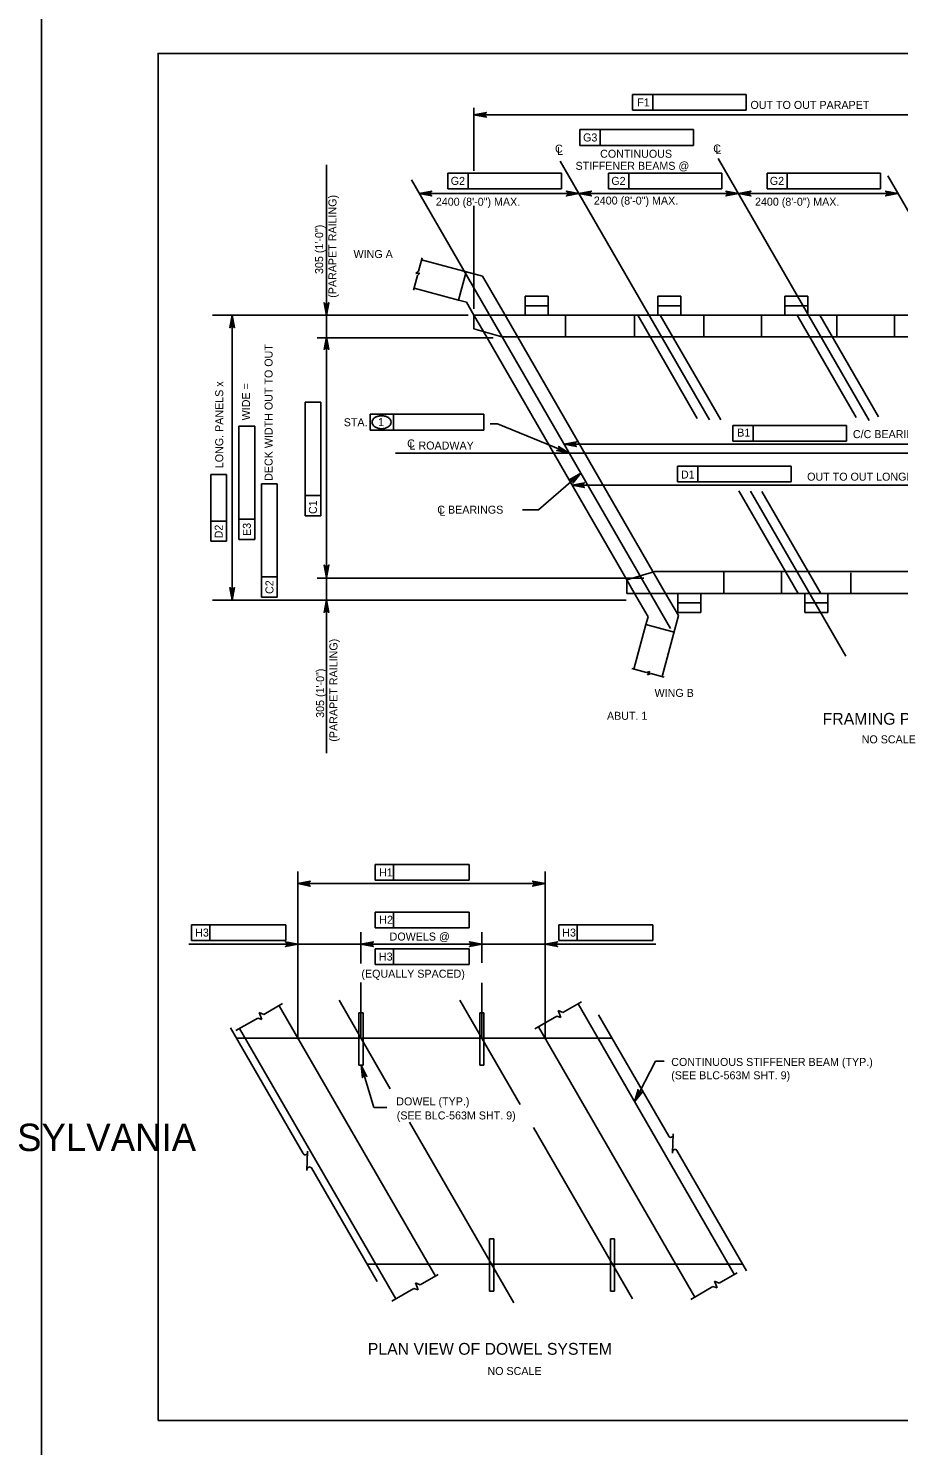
# Model space of a CAD drawing. Extents: x -8 to 75, y -110 to 0.
# Drawn here: x 33.8 to 46.85, y -65.62 to -44.38 of the extents above; entities that cross this region are included whole.
import ezdxf

# ---------------------------------------------------------------- set-up
doc = ezdxf.new("R2010")
doc.units = 0
for name, color, linetype in [('1', 7, 'Continuous'), ('2', 7, 'Continuous'), ('3', 7, 'Continuous'), ('4', 7, 'Continuous'), ('63', 7, 'Continuous')]:
    doc.layers.add(name, color=color, linetype=linetype)

# ---------------------------------------------------------------- blocks, each defined once
blk = doc.blocks.new('D')
at = {"layer": '3'}
for p, q in [((-0.324, 0.383), (-0.383, 0.324)), ((0.349, -0.408), (-0.383, 0.324)), ((0.408, -0.349), (-0.324, 0.383)), ((0.408, -0.349), (0.349, -0.408))]:
    blk.add_line(p, q, dxfattribs=at)

msp = doc.modelspace()

# ---------------------------------------------------------------- linework, layer by layer
at = {"layer": '1'}
msp.add_lwpolyline([(35.75, -65.25), (67.25, -65.25), (67.25, -44.75), (35.75, -44.75)], close=True, dxfattribs=at)
at = {"layer": '2'}
for p, q in [((40.615, -48.093), (39.7, -47.848)), ((40.255, -48.448), (40.367, -48.026)), ((40.953, -48.677), (40.615, -48.093)), ((40.255, -48.448), (39.587, -48.269)), ((40.373, -48.48), (40.255, -48.448)), ((41.252, -48.388), (41.252, -48.677)), ((41.598, -48.388), (41.252, -48.388)), ((41.598, -48.388), (41.598, -48.677)), ((43.588, -48.388), (43.242, -48.388)), ((43.242, -48.388), (43.242, -48.677)), ((43.588, -48.388), (43.588, -48.677)), ((45.146, -48.388), (45.492, -48.388)), ((45.146, -48.388), (45.146, -48.677)), ((45.492, -48.388), (45.492, -48.677)), ((40.373, -48.48), (40.486, -48.677)), ((40.486, -48.677), (48.247, -48.677)), ((40.486, -48.677), (40.627, -48.92)), ((40.486, -48.879), (40.486, -48.677)), ((40.953, -48.677), (43.359, -52.846)), ((40.906, -49.001), (40.486, -48.879)), ((40.627, -48.92), (42.777, -52.644)), ((47.828, -49.001), (40.906, -49.001)), ((43.196, -52.521), (42.777, -52.644)), ((42.777, -52.644), (42.777, -52.846)), ((42.777, -52.644), (42.893, -52.846)), ((50.118, -52.521), (43.196, -52.521)), ((42.777, -52.846), (50.537, -52.846)), ((42.893, -52.846), (43.096, -53.196)), ((43.552, -53.179), (43.359, -52.846)), ((43.542, -53.134), (43.542, -52.846)), ((43.888, -53.134), (43.888, -52.846)), ((45.445, -53.134), (45.445, -52.846)), ((45.791, -53.134), (45.791, -52.846)), ((43.064, -53.315), (42.885, -53.982)), ((43.096, -53.196), (43.064, -53.315)), ((43.064, -53.315), (43.486, -53.427)), ((43.552, -53.179), (43.307, -54.095)), ((43.888, -53.134), (43.542, -53.134)), ((45.791, -53.134), (45.445, -53.134)), ((42.557, -59.516), (36.923, -59.516)), ((44.515, -62.904), (38.882, -62.904))]:
    msp.add_line(p, q, dxfattribs=at)
at = {"layer": '3'}
for p, q in [((39.655, -48.018), (39.614, -48.049)), ((39.655, -48.018), (39.708, -47.818)), ((39.579, -48.302), (39.637, -48.083)), ((39.614, -48.049), (39.672, -48.045)), ((39.672, -48.045), (39.637, -48.083)), ((41.598, -48.533), (41.252, -48.533)), ((43.588, -48.533), (43.242, -48.533)), ((45.146, -48.533), (45.492, -48.533)), ((41.857, -49.001), (41.857, -48.677)), ((42.895, -49.001), (42.895, -48.677)), ((42.941, -48.677), (43.834, -50.224)), ((43.279, -48.677), (44.186, -50.247)), ((43.934, -49.001), (43.934, -48.677)), ((44.799, -49.001), (44.799, -48.677)), ((45.333, -48.677), (46.218, -50.209)), ((45.672, -48.677), (46.551, -50.199)), ((45.925, -49.001), (45.925, -48.677)), ((46.79, -49.001), (46.79, -48.677)), ((44.46, -51.309), (45.348, -52.846)), ((44.804, -51.319), (45.686, -52.846)), ((44.234, -52.521), (44.234, -52.846)), ((45.099, -52.521), (45.099, -52.846)), ((46.138, -52.846), (46.138, -52.537)), ((43.888, -52.99), (43.542, -52.99)), ((45.791, -52.99), (45.445, -52.99)), ((42.853, -53.973), (43.072, -54.032)), ((43.122, -54.02), (43.072, -54.032)), ((43.09, -54.069), (43.122, -54.02)), ((43.137, -54.049), (43.09, -54.069)), ((43.137, -54.049), (43.337, -54.103)), ((37.337, -59.159), (37.617, -58.997)), ((37.563, -59.029), (39.907, -63.083)), ((39.23, -60.274), (38.464, -58.947)), ((41.181, -60.512), (40.276, -58.947)), ((41.82, -59.133), (42.1, -58.97)), ((42.046, -59.002), (44.39, -63.056)), ((36.917, -59.402), (37.243, -59.214)), ((37.243, -59.214), (37.305, -59.234)), ((37.305, -59.234), (37.265, -59.13)), ((37.265, -59.13), (37.337, -59.159)), ((41.4, -59.375), (41.726, -59.187)), ((41.726, -59.187), (41.788, -59.207)), ((41.748, -59.103), (41.82, -59.133)), ((41.788, -59.207), (41.748, -59.103)), ((42.354, -59.165), (43.406, -60.984)), ((36.833, -59.36), (37.924, -61.247)), ((39.313, -63.426), (36.97, -59.371)), ((43.797, -63.399), (41.453, -59.344)), ((38.76, -59.516), (38.823, -59.516)), ((40.573, -59.516), (40.636, -59.516)), ((41.086, -63.485), (39.52, -60.774)), ((42.863, -63.422), (41.378, -60.854)), ((43.474, -60.948), (43.463, -61.239)), ((43.53, -61.2), (44.573, -63.003)), ((37.992, -61.21), (37.982, -61.501)), ((38.048, -61.462), (39.032, -63.164)), ((39.68, -63.214), (39.948, -63.059)), ((44.163, -63.187), (44.431, -63.032)), ((39.254, -63.46), (39.586, -63.268)), ((39.586, -63.268), (39.649, -63.288)), ((39.608, -63.184), (39.68, -63.214)), ((39.649, -63.288), (39.608, -63.184)), ((43.737, -63.433), (44.07, -63.241)), ((44.07, -63.241), (44.132, -63.261)), ((44.091, -63.157), (44.163, -63.187)), ((44.132, -63.261), (44.091, -63.157))]:
    msp.add_line(p, q, dxfattribs=at)
for centre, start, end in [((43.437, -60.966), 210.0292, 0.0292), ((43.501, -61.221), 35.3578, 177.8964), ((37.956, -61.229), 210.0292, 0.0292), ((38.019, -61.483), 35.3578, 177.8964)]:
    msp.add_arc(centre, 0.0364, start, end, dxfattribs=at)
at = {"layer": '4'}
for p, q in [((42.865, -45.367), (44.566, -45.367)), ((42.865, -45.367), (42.865, -45.604)), ((43.167, -45.367), (43.167, -45.604)), ((44.566, -45.367), (44.566, -45.604)), ((40.486, -46.51), (40.486, -45.569)), ((40.486, -45.671), (48.247, -45.671)), ((42.865, -45.604), (44.566, -45.604)), ((42.075, -45.893), (43.776, -45.893)), ((42.075, -45.893), (42.075, -46.13)), ((42.378, -45.893), (42.378, -46.13)), ((43.776, -45.893), (43.776, -46.13)), ((42.075, -46.13), (43.776, -46.13)), ((44.147, -46.324), (46.412, -50.253)), ((38.274, -46.42), (38.274, -55.241)), ((41.779, -46.367), (44.016, -50.246)), ((43.432, -53.374), (39.548, -46.647)), ((40.095, -46.544), (41.796, -46.544)), ((40.095, -46.544), (40.095, -46.78)), ((40.398, -46.544), (40.398, -46.78)), ((41.796, -46.544), (41.796, -46.78)), ((42.503, -46.544), (44.204, -46.544)), ((42.503, -46.544), (42.503, -46.78)), ((42.806, -46.544), (42.806, -46.78)), ((44.204, -46.544), (44.204, -46.78)), ((44.881, -46.544), (46.582, -46.544)), ((44.881, -46.544), (44.881, -46.78)), ((45.183, -46.544), (45.183, -46.78)), ((46.582, -46.544), (46.582, -46.78)), ((50.637, -53.422), (46.69, -46.585)), ((39.666, -46.852), (46.844, -46.852)), ((40.095, -46.78), (41.796, -46.78)), ((42.503, -46.78), (44.204, -46.78)), ((44.881, -46.78), (46.582, -46.78)), ((40.486, -48.581), (40.486, -47.035)), ((40.401, -48.677), (36.564, -48.677)), ((36.86, -52.946), (36.86, -48.677)), ((40.772, -49.015), (38.134, -49.015)), ((37.953, -51.683), (37.953, -49.982)), ((38.19, -49.982), (37.953, -49.982)), ((38.19, -51.683), (38.19, -49.982)), ((36.962, -52.039), (36.962, -50.338)), ((37.198, -50.338), (36.962, -50.338)), ((37.198, -52.039), (37.198, -50.338)), ((38.931, -50.162), (40.632, -50.162)), ((38.931, -50.398), (38.931, -50.162)), ((39.281, -50.398), (39.281, -50.162)), ((40.632, -50.162), (40.632, -50.398)), ((40.84, -50.303), (40.73, -50.303)), ((40.843, -50.303), (40.73, -50.303)), ((41.914, -50.745), (40.84, -50.303)), ((44.369, -50.328), (46.07, -50.328)), ((44.369, -50.328), (44.369, -50.564)), ((44.672, -50.328), (44.672, -50.564)), ((46.07, -50.328), (46.07, -50.564)), ((40.632, -50.398), (38.931, -50.398)), ((44.369, -50.564), (46.07, -50.564)), ((51.399, -50.745), (39.31, -50.745)), ((41.836, -50.61), (49.014, -50.61)), ((43.539, -50.938), (45.24, -50.938)), ((43.539, -50.938), (43.539, -51.174)), ((43.842, -50.938), (43.842, -51.174)), ((45.24, -50.938), (45.24, -51.174)), ((36.54, -52.065), (36.54, -51.063)), ((36.776, -51.063), (36.54, -51.063)), ((36.776, -52.065), (36.776, -51.063)), ((37.301, -52.903), (37.301, -51.203)), ((37.537, -51.203), (37.301, -51.203)), ((37.537, -52.904), (37.537, -51.203)), ((41.453, -51.595), (42.086, -51.044)), ((43.539, -51.174), (45.24, -51.174)), ((38.19, -51.38), (37.953, -51.38)), ((41.956, -51.222), (49.6, -51.222)), ((44.633, -51.315), (46.06, -53.787)), ((41.214, -51.595), (41.453, -51.595)), ((36.776, -51.763), (36.54, -51.762)), ((37.198, -51.736), (36.962, -51.736)), ((37.953, -51.683), (38.19, -51.683)), ((36.962, -52.039), (37.198, -52.039)), ((36.54, -52.065), (36.776, -52.065)), ((37.537, -52.601), (37.301, -52.601)), ((43.035, -52.62), (38.134, -52.62)), ((37.301, -52.903), (37.537, -52.904)), ((42.77, -52.946), (36.564, -52.946)), ((39.003, -56.91), (40.415, -56.91)), ((39.003, -56.91), (39.003, -57.146)), ((39.278, -56.91), (39.278, -57.146)), ((40.415, -56.91), (40.415, -57.146)), ((37.844, -59.453), (37.844, -57.019)), ((40.415, -57.146), (39.003, -57.146)), ((41.552, -59.453), (41.552, -57.019)), ((41.552, -57.199), (37.844, -57.199)), ((39.003, -57.625), (39.003, -57.861)), ((39.003, -57.625), (40.415, -57.625)), ((39.278, -57.625), (39.278, -57.861)), ((40.415, -57.625), (40.415, -57.861)), ((36.252, -57.816), (37.664, -57.816)), ((36.252, -57.816), (36.252, -58.053)), ((36.527, -57.816), (36.527, -58.053)), ((37.664, -57.816), (37.664, -58.053)), ((37.844, -59.516), (37.844, -57.927)), ((38.791, -58.397), (38.791, -57.927)), ((40.415, -57.861), (39.003, -57.861)), ((40.604, -58.386), (40.604, -57.927)), ((41.552, -59.516), (41.552, -57.927)), ((41.757, -57.816), (43.169, -57.816)), ((41.757, -57.816), (41.757, -58.053)), ((42.033, -57.816), (42.033, -58.053)), ((43.169, -57.816), (43.169, -58.053)), ((37.724, -58.107), (36.209, -58.107)), ((37.664, -58.053), (36.252, -58.053)), ((38.791, -58.107), (37.843, -58.107)), ((40.484, -58.107), (38.911, -58.107)), ((39.003, -58.176), (40.415, -58.176)), ((39.003, -58.176), (39.003, -58.412)), ((39.278, -58.176), (39.278, -58.412)), ((40.484, -58.107), (40.364, -58.107)), ((40.415, -58.176), (40.415, -58.412)), ((41.552, -58.107), (40.604, -58.107)), ((41.672, -58.107), (43.215, -58.107)), ((43.169, -58.053), (41.757, -58.053)), ((40.415, -58.412), (39.003, -58.412)), ((38.791, -59.516), (38.791, -58.68)), ((40.604, -59.516), (40.604, -58.686)), ((43.209, -59.861), (43.339, -59.861)), ((38.987, -60.556), (39.181, -60.556))]:
    msp.add_line(p, q, dxfattribs=at)
for points in [[(40.486, -45.671), (40.673, -45.636), (40.658, -45.646), (40.651, -45.658), (40.649, -45.671), (40.651, -45.683), (40.658, -45.696), (40.673, -45.706), (40.486, -45.671), (40.658, -45.696), (40.651, -45.683), (40.486, -45.671), (40.649, -45.671), (40.651, -45.658), (40.486, -45.671), (40.658, -45.646)], [(39.666, -46.852), (39.853, -46.817), (39.838, -46.827), (39.831, -46.84), (39.829, -46.852), (39.831, -46.865), (39.838, -46.877), (39.853, -46.887), (39.666, -46.852), (39.838, -46.877), (39.831, -46.865), (39.666, -46.852), (39.829, -46.852), (39.831, -46.84), (39.666, -46.852), (39.838, -46.827)], [(42.059, -46.852), (41.873, -46.887), (41.887, -46.877), (41.895, -46.865), (41.897, -46.852), (41.895, -46.84), (41.887, -46.827), (41.873, -46.817), (42.059, -46.852), (41.887, -46.827), (41.895, -46.84), (42.059, -46.852), (41.897, -46.852), (41.895, -46.865), (42.059, -46.852), (41.887, -46.877)], [(42.059, -46.852), (42.246, -46.887), (42.231, -46.877), (42.224, -46.865), (42.222, -46.852), (42.224, -46.84), (42.231, -46.827), (42.246, -46.817), (42.059, -46.852), (42.231, -46.827), (42.224, -46.84), (42.059, -46.852), (42.222, -46.852), (42.224, -46.865), (42.059, -46.852), (42.231, -46.877)], [(44.452, -46.852), (44.265, -46.887), (44.28, -46.877), (44.287, -46.865), (44.289, -46.852), (44.287, -46.84), (44.28, -46.827), (44.265, -46.817), (44.452, -46.852), (44.28, -46.827), (44.287, -46.84), (44.452, -46.852), (44.289, -46.852), (44.287, -46.865), (44.452, -46.852), (44.28, -46.877)], [(44.452, -46.852), (44.638, -46.887), (44.624, -46.877), (44.616, -46.865), (44.614, -46.852), (44.616, -46.84), (44.624, -46.827), (44.638, -46.817), (44.452, -46.852), (44.624, -46.827), (44.616, -46.84), (44.452, -46.852), (44.614, -46.852), (44.616, -46.865), (44.452, -46.852), (44.624, -46.877)], [(46.844, -46.852), (46.657, -46.887), (46.672, -46.877), (46.679, -46.865), (46.681, -46.852), (46.679, -46.84), (46.672, -46.827), (46.657, -46.817), (46.844, -46.852), (46.672, -46.827), (46.679, -46.84), (46.844, -46.852), (46.681, -46.852), (46.679, -46.865), (46.844, -46.852), (46.672, -46.877)], [(38.274, -48.677), (38.239, -48.49), (38.249, -48.505), (38.261, -48.512), (38.274, -48.514), (38.286, -48.512), (38.299, -48.505), (38.309, -48.49), (38.274, -48.677), (38.299, -48.505), (38.286, -48.512), (38.274, -48.677), (38.274, -48.514), (38.261, -48.512), (38.274, -48.677), (38.249, -48.505)], [(36.86, -48.677), (36.895, -48.863), (36.885, -48.849), (36.873, -48.841), (36.86, -48.839), (36.848, -48.841), (36.835, -48.849), (36.825, -48.863), (36.86, -48.677), (36.835, -48.849), (36.848, -48.841), (36.86, -48.677), (36.86, -48.839), (36.873, -48.841), (36.86, -48.677), (36.885, -48.849)], [(38.274, -49.003), (38.309, -49.189), (38.299, -49.175), (38.286, -49.168), (38.274, -49.166), (38.261, -49.168), (38.249, -49.175), (38.239, -49.189), (38.274, -49.003), (38.249, -49.175), (38.261, -49.168), (38.274, -49.003), (38.274, -49.166), (38.286, -49.168), (38.274, -49.003), (38.299, -49.175)], [(41.914, -50.745), (41.728, -50.706), (41.745, -50.703), (41.757, -50.694), (41.763, -50.683), (41.766, -50.671), (41.764, -50.656), (41.755, -50.642), (41.914, -50.745), (41.764, -50.656), (41.766, -50.671), (41.914, -50.745), (41.763, -50.683), (41.757, -50.694), (41.914, -50.745), (41.745, -50.703)], [(41.836, -50.61), (42.022, -50.575), (42.008, -50.585), (42, -50.598), (41.998, -50.61), (42, -50.623), (42.008, -50.635), (42.022, -50.645), (41.836, -50.61), (42.008, -50.635), (42, -50.623), (41.836, -50.61), (41.998, -50.61), (42, -50.598), (41.836, -50.61), (42.008, -50.585)], [(42.086, -51.044), (41.969, -51.193), (41.973, -51.176), (41.97, -51.162), (41.964, -51.151), (41.954, -51.143), (41.94, -51.138), (41.923, -51.14), (42.086, -51.044), (41.94, -51.138), (41.954, -51.143), (42.086, -51.044), (41.964, -51.151), (41.97, -51.162), (42.086, -51.044), (41.973, -51.176)], [(41.956, -51.222), (42.142, -51.187), (42.128, -51.197), (42.121, -51.21), (42.118, -51.222), (42.121, -51.235), (42.128, -51.247), (42.142, -51.257), (41.956, -51.222), (42.128, -51.247), (42.121, -51.235), (41.956, -51.222), (42.118, -51.222), (42.121, -51.21), (41.956, -51.222), (42.128, -51.197)], [(38.276, -52.61), (38.241, -52.423), (38.251, -52.438), (38.263, -52.445), (38.276, -52.447), (38.288, -52.445), (38.301, -52.438), (38.31, -52.423), (38.276, -52.61), (38.301, -52.438), (38.288, -52.445), (38.276, -52.61), (38.276, -52.447), (38.263, -52.445), (38.276, -52.61), (38.251, -52.438)], [(36.86, -52.946), (36.825, -52.759), (36.835, -52.774), (36.848, -52.781), (36.86, -52.783), (36.873, -52.781), (36.885, -52.774), (36.895, -52.759), (36.86, -52.946), (36.885, -52.774), (36.873, -52.781), (36.86, -52.946), (36.86, -52.783), (36.848, -52.781), (36.86, -52.946), (36.835, -52.774)], [(38.274, -52.946), (38.309, -53.132), (38.299, -53.118), (38.286, -53.11), (38.274, -53.108), (38.261, -53.11), (38.249, -53.118), (38.239, -53.132), (38.274, -52.946), (38.249, -53.118), (38.261, -53.11), (38.274, -52.946), (38.274, -53.108), (38.286, -53.11), (38.274, -52.946), (38.299, -53.118)], [(37.844, -57.199), (38.031, -57.164), (38.017, -57.174), (38.009, -57.186), (38.007, -57.199), (38.009, -57.211), (38.017, -57.224), (38.031, -57.234), (37.844, -57.199), (38.017, -57.224), (38.009, -57.211), (37.844, -57.199), (38.007, -57.199), (38.009, -57.186), (37.844, -57.199), (38.017, -57.174)], [(41.552, -57.199), (41.366, -57.234), (41.38, -57.224), (41.387, -57.211), (41.39, -57.199), (41.387, -57.186), (41.38, -57.174), (41.366, -57.164), (41.552, -57.199), (41.38, -57.174), (41.387, -57.186), (41.552, -57.199), (41.39, -57.199), (41.387, -57.211), (41.552, -57.199), (41.38, -57.224)], [(37.844, -58.107), (37.658, -58.142), (37.672, -58.132), (37.68, -58.12), (37.682, -58.107), (37.68, -58.095), (37.672, -58.082), (37.658, -58.072), (37.844, -58.107), (37.672, -58.082), (37.68, -58.095), (37.844, -58.107), (37.682, -58.107), (37.68, -58.12), (37.844, -58.107), (37.672, -58.132)], [(38.791, -58.107), (38.978, -58.072), (38.963, -58.082), (38.956, -58.095), (38.954, -58.107), (38.956, -58.12), (38.963, -58.132), (38.978, -58.142), (38.791, -58.107), (38.963, -58.132), (38.956, -58.12), (38.791, -58.107), (38.954, -58.107), (38.956, -58.095), (38.791, -58.107), (38.963, -58.082)], [(40.604, -58.107), (40.418, -58.142), (40.432, -58.132), (40.439, -58.12), (40.442, -58.107), (40.439, -58.095), (40.432, -58.082), (40.418, -58.072), (40.604, -58.107), (40.432, -58.082), (40.439, -58.095), (40.604, -58.107), (40.442, -58.107), (40.439, -58.12), (40.604, -58.107), (40.432, -58.132)], [(41.552, -58.107), (41.739, -58.072), (41.724, -58.082), (41.717, -58.095), (41.715, -58.107), (41.717, -58.12), (41.724, -58.132), (41.739, -58.142), (41.552, -58.107), (41.724, -58.132), (41.717, -58.12), (41.552, -58.107), (41.715, -58.107), (41.717, -58.095), (41.552, -58.107), (41.724, -58.082)], [(38.792, -59.92), (38.986, -60.556)], [(38.792, -59.92), (38.813, -60.108), (38.819, -60.092), (38.828, -60.081), (38.84, -60.075), (38.852, -60.074), (38.867, -60.077), (38.88, -60.088), (38.792, -59.92), (38.867, -60.077), (38.852, -60.074), (38.792, -59.92), (38.84, -60.075), (38.828, -60.081), (38.792, -59.92), (38.819, -60.092)], [(42.894, -60.468), (43.209, -59.861)], [(42.894, -60.468), (43.011, -60.318), (42.995, -60.326), (42.98, -60.327), (42.968, -60.323), (42.958, -60.316), (42.951, -60.303), (42.948, -60.286), (42.894, -60.468), (42.951, -60.303), (42.958, -60.316), (42.894, -60.468), (42.968, -60.323), (42.98, -60.327), (42.894, -60.468), (42.995, -60.326)]]:
    msp.add_lwpolyline(points, dxfattribs=at)
for points in [[(36.841, -48.79), (36.879, -48.79), (36.86, -48.677)], [(41.804, -50.72), (41.818, -50.686), (41.914, -50.745)], [(36.841, -52.832), (36.879, -52.832), (36.86, -52.946)], [(37.965, -57.179), (37.965, -57.219), (37.844, -57.199)], [(41.432, -57.179), (41.432, -57.219), (41.552, -57.199)], [(37.724, -58.087), (37.724, -58.127), (37.844, -58.107)], [(38.911, -58.087), (38.911, -58.127), (38.791, -58.107)], [(40.484, -58.087), (40.484, -58.127), (40.604, -58.107)], [(41.672, -58.087), (41.672, -58.127), (41.552, -58.107)], [(38.792, -59.92), (38.837, -60.032), (38.818, -60.038)], [(42.894, -60.468), (42.94, -60.357), (42.958, -60.366)]]:
    msp.add_lwpolyline(points, close=True, dxfattribs=at)
for centre, radius, start, end in [((39.024, -50.28), 0.067, 148.5507, 180), ((39.024, -50.28), 0.067, 180, 211.4493), ((39.061, -50.303), 0.11, 124.109, 148.5507), ((39.061, -50.258), 0.11, 211.4493, 235.891), ((39.085, -50.338), 0.153, 105.6708, 124.109), ((39.085, -50.223), 0.153, 235.891, 254.3292), ((39.1, -50.394), 0.211, 90, 105.6708), ((39.1, -50.394), 0.211, 74.3292, 90), ((39.116, -50.338), 0.153, 55.891, 74.3292), ((39.116, -50.223), 0.153, 285.6708, 304.109), ((39.14, -50.303), 0.11, 31.4493, 55.891), ((39.14, -50.258), 0.11, 304.109, 328.5507), ((39.177, -50.28), 0.067, 0, 31.4493), ((39.177, -50.28), 0.067, 328.5507, 0), ((39.1, -50.167), 0.211, 254.3292, 270), ((39.1, -50.167), 0.211, 270, 285.6708)]:
    msp.add_arc(centre, radius, start, end, dxfattribs=at)
at = {"layer": '63'}
for points in [[(0, -66), (34, -66), (34, -44), (0, -44)], [(34, -66), (68, -66), (68, -44), (34, -44)]]:
    msp.add_lwpolyline(points, close=True, dxfattribs=at)

# ---------------------------------------------------------------- block references
at = {"layer": '4', "xscale": 0.7559417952, "yscale": 0.7559417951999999, "rotation": -44.99995150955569}
for p in [(38.792, -59.516), (40.604, -59.516), (40.75, -62.904), (42.563, -62.904)]:
    msp.add_blockref('D', p, dxfattribs=at)

# ---------------------------------------------------------------- texts
at = {"layer": '1'}
msp.add_text('COMMONWEALTH OF PENNSYLVANIA', height=0.41038, dxfattribs=at).set_placement((26.196, -61.208))
at = {"layer": '4'}
for s, rotation, p in [('F1', 359.9382, (42.934, -45.545)), ('G3', 359.9382, (42.122, -46.071)), ('G2', 359.9382, (40.137, -46.722)), ('G2', 359.9382, (42.545, -46.722)), ('G2', 359.9382, (44.922, -46.722)), ('(PARAPET RAILING)', 90, (38.424, -48.415)), ('2400 (8\'-0") MAX.', 359.9382, (39.914, -47.034)), ('2400 (8\'-0") MAX.', 359.9382, (42.283, -47.017)), ('2400 (8\'-0") MAX.', 359.9382, (44.7, -47.034)), ('305 (1\'-0")', 90, (38.224, -48.058)), ('DECK WIDTH OUT TO OUT', 90, (37.466, -51.16)), ('LONG. PANELS x', 90, (36.726, -50.97)), ('WIDE =', 90, (37.127, -50.252)), ('B1', 359.9382, (44.434, -50.496)), ('D1', 359.9382, (43.59, -51.125)), ('C1', 89.9382, (38.131, -51.657)), ('D2', 89.9382, (36.718, -52.022)), ('E3', 89.9382, (37.14, -51.986)), ('C2', 89.9382, (37.479, -52.856)), ('(PARAPET RAILING)', 90, (38.439, -55.07)), ('305 (1\'-0")', 90, (38.239, -54.713))]:
    msp.add_text(s, height=0.12, rotation=rotation, dxfattribs=at).set_placement(p)
for s, height, p in [('OUT TO OUT PARAPET ', 0.12, (44.632, -45.583)), ('C', 0.12, (41.701, -46.239)), ('L', 0.12, (41.734, -46.274)), ('CONTINUOUS', 0.12, (42.378, -46.315)), ('C', 0.12, (44.074, -46.237)), ('L', 0.12, (44.106, -46.26)), ('STIFFENER BEAMS @', 0.12, (42.009, -46.496)), ('WING A', 0.12, (38.68, -47.819)), ('STA.', 0.12, (38.533, -50.341)), ('1', 0.12, (39.048, -50.338)), ('C', 0.12, (39.484, -50.659)), ('L ROADWAY', 0.12, (39.52, -50.69)), ('C/C BEARINGS', 0.12, (46.168, -50.519)), ('OUT TO OUT LONGITUDINAL PANEL', 0.12, (45.482, -51.157)), ('C BEARINGS', 0.12, (39.936, -51.652)), ('L', 0.12, (39.966, -51.683)), ('WING B', 0.12, (43.194, -54.399)), ('ABUT. 1', 0.12, (42.48, -54.742)), ('FRAMING PLAN', 0.17717, (45.714, -54.816)), ('NO SCALE', 0.12, (46.3, -55.095)), ('H1', 0.12, (39.062, -57.091)), ('H2', 0.12, (39.066, -57.801)), ('H3', 0.12, (36.305, -57.992)), ('DOWELS @', 0.12, (39.221, -58.052)), ('H3', 0.12, (41.81, -57.992)), ('H3', 0.12, (39.061, -58.352)), ('(EQUALLY SPACED)', 0.12, (38.798, -58.609)), ('CONTINUOUS STIFFENER BEAM (TYP.)', 0.12, (43.444, -59.932)), ('(SEE BLC-563M SHT. 9)', 0.12, (43.444, -60.132)), ('DOWEL (TYP.)', 0.12, (39.321, -60.523)), ('(SEE BLC-563M SHT. 9)', 0.12, (39.328, -60.734)), ('PLAN VIEW OF DOWEL SYSTEM', 0.17717, (38.894, -64.262)), ('NO SCALE', 0.12, (40.688, -64.566))]:
    msp.add_text(s, height=height, dxfattribs=at).set_placement(p)

doc.saveas('drawing.dxf')
